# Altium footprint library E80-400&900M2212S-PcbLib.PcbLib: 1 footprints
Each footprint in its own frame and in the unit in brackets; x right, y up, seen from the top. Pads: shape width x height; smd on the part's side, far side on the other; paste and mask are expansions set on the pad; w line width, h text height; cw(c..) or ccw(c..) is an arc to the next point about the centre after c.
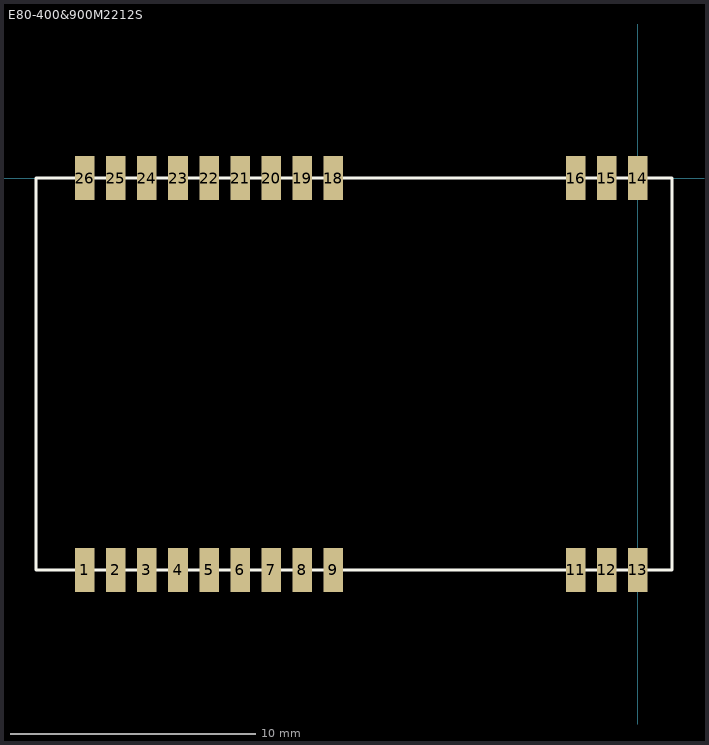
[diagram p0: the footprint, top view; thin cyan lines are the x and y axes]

## E80-400&900M2212S [mm] "26mm**16mm*3.23mm-S"
pads (24):
  rect 0.8x1.8 smd: 1(-22.6,-16) 2(-21.33,-16) 3(-20.06,-16) 4(-18.79,-16) 5(-17.52,-16) 6(-16.25,-16) 7(-14.98,-16) 8(-13.71,-16) 9(-12.44,-16) 11(-2.54,-16) 12(-1.27,-16) 13(0,-16) 14(0,0) 15(-1.27,0) 16(-2.54,0) 18(-12.44,0) 19(-13.71,0) 20(-14.98,0) 21(-16.25,0) 22(-17.52,0) 23(-18.79,0) 24(-20.06,0) 25(-21.33,0) 26(-22.6,0)
Top Overlay:
  lines w0.127: -24.6,-16 1.4,-16 1.4,0 -24.6,0 -24.6,-16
